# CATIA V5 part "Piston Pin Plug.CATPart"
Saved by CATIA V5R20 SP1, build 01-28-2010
Part number: Piston Pin Plug
Bounding box of the stored display mesh (mm): x -11 to 11, y -10.833 to 10.833, z -15 to 0
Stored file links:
  D:\v5_r20\psrt_files_downloaded\c13-catia-v5r20-prt\c13-catia-v5r20-figr-13-41\Part & Asm files\Piston Pin Plug.CATPart
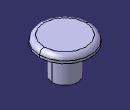
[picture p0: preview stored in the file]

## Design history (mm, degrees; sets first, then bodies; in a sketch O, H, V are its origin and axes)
Body1 (main body)
  Sketch1 on xy-plane, origin (0, 0, 0), H (1, 0, 0), V (0, 1, 0)
    circle A1 centre (0, 0) radius 11
    circle A2 centre (0, 0) radius 5.5
    radius A2 = 5.5
    radius A1 = 11
  MultiPad1: profile Sketch1, domains (length 15; length 3)
  Fillet1: radius 2, on 1 edge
